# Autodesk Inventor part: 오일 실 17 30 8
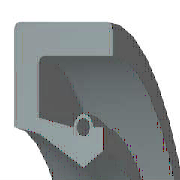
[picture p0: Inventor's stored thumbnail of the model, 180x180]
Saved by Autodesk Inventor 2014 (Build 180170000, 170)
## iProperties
Created: 2012-02
Part Number: 오일 실 17 30 8
Material: 고무
Description: 오일-실
Document SubType Name: Modeling
Standard: KS B 2804
Designer: mduedu
Standards Organization: KS
Language: ko-KR
Size Designation: S - 17 30 8
Categories: <MemberInstance><Categories><Category DisplayName="샤프트 부품" InternalName="7f7aeb1f-a693-4053-b835-cee3144e0d98" Mnemonic="SHFT"><Category DisplayName="실링" Intern
Density: 0.93 g/cm^3
Appearance: Rubber - Black - Version 1.1
IsCustomPart: 1
Author: mduedu
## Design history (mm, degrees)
revolve "본체" stored, may be unused: angle "d17" = 90 deg
revolve "스프링1" stored, may be unused: angle "d18" = 90 deg
body "Solid1"
sketch "스케치1"
  geometry: L1 (0, 15)-(8, 15); L2 (8, 15)-(8, 13.75); L3 (8, 13.75)-(1.75, 13.75); L4 (0, 15)-(0, 10.6); L5 (0, 10.6)-(1.75, 10.25); L6 (1.75, 10.25)-(4.9, 8.5); L7 (4.9, 8.5)-(0, 8.5); L8 (6.3, 9.375)-(6.3, 10.6); L9 (0, 0)-(9.586, 0) reference; L10 (4.9, 8.5)-(6.3, 9.375); L11 (0, 18)-(0, -3) reference; L12 (-1.917, 0)-(11.503, 0) reference; L13 (4.2, 10.6)-(1.75, 11.09); L14 (1.75, 11.09)-(1.75, 13.75); L15 (6.3, 10.6)-(5.6, 10.6); C1 r 0.455 at (4.9, 10.6); A1 r 0.7 centre (4.9, 10.6) between (5.6, 10.6) and (4.2, 10.6)
  constraints: 26 end point, 5 horizontal alignment, 4 perpendicular, 2 centre point, 2 collinear, 2 horizontal, 2 parallel, 2 point on circle, 2 point on line, 2 vertical alignment, 1 coincident
  dimensions: "d0" = 30 diameter of L1 L9 (= SD2); "d1" = 18.75 diameter of L8.start L9 (= ABDM); "d2" = 1.25 distance of L1.end L2.end (computed from SD); "d3" = 0.91 diameter of C1 (= SPDI); "d4" = 1.4 diameter of A1 (= SPDA); "d5" = 17 diameter of L6.end L9 (= NND); "d6" = 20.5 diameter of L5.end L9 (= TKDM); "d7" = 21.2 diameter of L4.end L9 (= HLDM); "d8" = 4.9 distance from line of C1.centre L4 (= SPDST); "d9" = 6.3 distance between parallel lines of L8 L4 (= SDI); "d10" = 8 distance between parallel lines of L2 L4 (= SWDT); "d12" = 1.75 distance between parallel lines of L14 L4 (= SD)
fillet "모깎기1" dims "d11" = 0.3 (= RR)
other parameters: "SD2" = 30 [user parameter; used in 1 equation term], "SWDT" = 8 [user parameter; used in 1 equation term], "RR" = 0.3 [user parameter; used in 1 equation term], "SD" = 1.75 [user parameter; used in 2 equation terms], "NND" = 17 [user parameter; used in 1 equation term], "SPDA" = 1.4 [user parameter; used in 1 equation term], "SPDI" = 0.91 [user parameter; used in 1 equation term], "TKDM" = 20.5 [user parameter; used in 1 equation term], "HLDM" = 21.2 [user parameter; used in 1 equation term], "ABDM" = 18.75 [user parameter; used in 1 equation term], "SDI" = 6.3 [user parameter; used in 1 equation term], "SPDST" = 4.9 [user parameter; used in 1 equation term], "d13" = 0, "d14" = 0, "d15" = 0, "LAB" = 0.35 [user parameter]
